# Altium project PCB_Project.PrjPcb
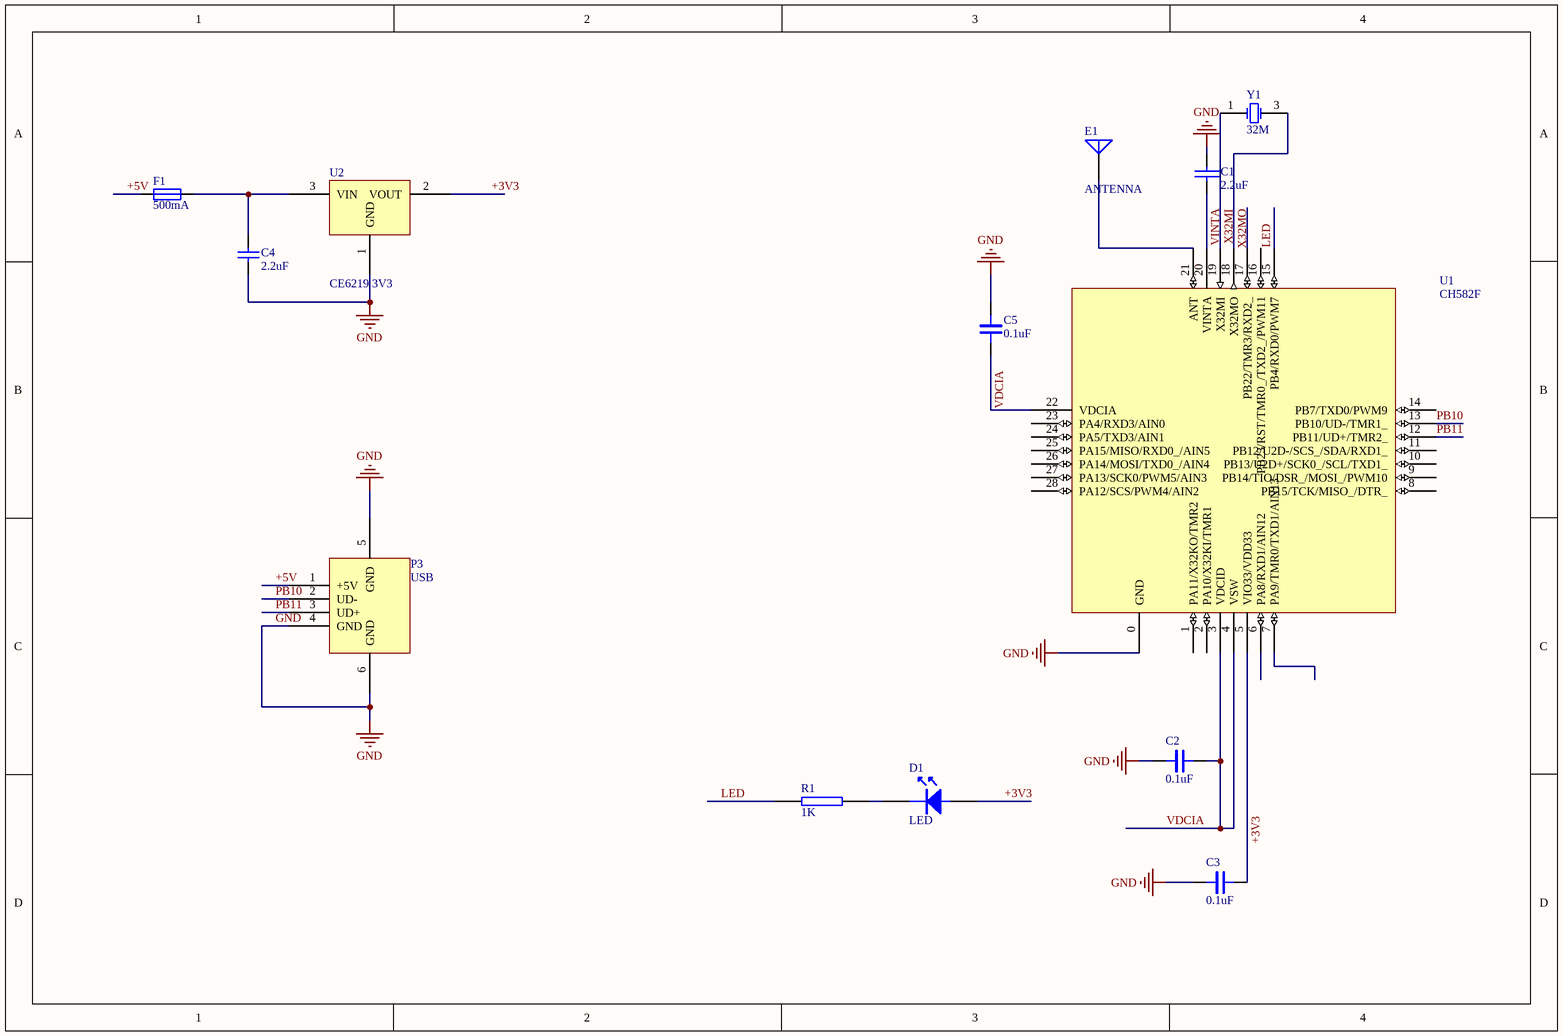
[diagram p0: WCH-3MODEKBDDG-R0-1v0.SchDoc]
1 sheet, 13 parts. Net scope: global (net labels, ports and power ports of the same name join across sheets).
Board file: WCH-3MODEKBDDG-R0-1v0.PcbDoc

## Sheet WCH-3MODEKBDDG-R0-1v0.SchDoc
size A4

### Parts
C1  2.2uF  [0402_C]
C2  0.1uF  [0402_C]
C3  0.1uF  [0402_C]
C4  2.2uF  [0402_C]
C5  0.1uF  [0402_C]
D1  LED  [0603+]
E1  ANTENNA  [ANT-F-1-2.4G-0.8]
F1  500mA  [0603]
P3  USB  [USBAM-4P]
R1  1K  [0402]
U1  CH582F  [QFN28_4X4]
U2  CE6219 3V3  [sot-23]
Y1  32M  [32M_2x1.6]

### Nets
GND: C1.1 C2.1 C3.1 C4.1 C5.2 P3.4(GND) P3.5(GND) P3.6(GND) U1.0(GND) U2.1(GND)
+3V3: C3.2 D1.1 U1.5(VIO33/VDD33) U2.2(VOUT)
+5V: F1.1 P3.1(+5V)
LED: R1.2 U1.15(PB4/RXD0/PWM7)
PB10: P3.2(UD-) U1.13(PB10/UD-/TMR1_)
PB11: P3.3(UD+) U1.12(PB11/UD+/TMR2_)
VDCIA: C2.2 C5.1 U1.3(VDCID) U1.4(VSW) U1.22(VDCIA)
VINTA: C1.2 U1.20(VINTA)
X32MI: U1.19(X32MI) Y1.1(OSC1)
X32MO: U1.18(X32MO) Y1.3(OSC2)
NetC4_2: C4.2 F1.2 U2.3(VIN)
NetD1_2: D1.2 R1.1
NetE1_1: E1.1(A) U1.21(ANT)

Not connected (* = marked no-connect by the designer): U1 1(PA11/X32KO/TMR2) 2(PA10/X32KI/TMR1) 6(PA8/RXD1/AIN12) 7(PA9/TMR0/TXD1/AIN13) 8(PB15/TCK/MISO_/DTR_) 9(PB14/TIO/DSR_/MOSI_/PWM10) 10(PB13/U2D+/SCK0_/SCL/TXD1_) 11(PB12/U2D-/SCS_/SDA/RXD1_) 14(PB7/TXD0/PWM9) 16(PB23/RST/TMR0_/TXD2_/PWM11) 17(PB22/TMR3/RXD2_) 23(PA4/RXD3/AIN0) 24(PA5/TXD3/AIN1) 25(PA15/MISO/RXD0_/AIN5) 26(PA14/MOSI/TXD0_/AIN4) 27(PA13/SCK0/PWM5/AIN3) 28(PA12/SCS/PWM4/AIN2)

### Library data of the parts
C1 = C0402
C2 C3 C5 = CAP: Capacitor
C4 = Cap: Capacitor; Value: 100pF
E1 = ANTENNA: Generic Antenna
F1 = FAF-0031.37xx: Fuse holder
R1 = RES2
U1 = CH582F: RISC-V MCU with BLE/2*USB/ADC/PWM/SPI/I2C/4*UART
Y1 = XTAL: Crystal Oscillator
